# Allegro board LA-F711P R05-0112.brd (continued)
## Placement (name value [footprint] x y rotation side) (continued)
CZ115  0.1U_0201_10V6K  [C_0201]  196.24 7.58 90 top
CZ116  0.1U_0201_10V6K  [C_0201]  285.91 9.49 90 top
CZ117  470P_0402_50V7K  [C_0402]  286.67 9.55 90 top
CZ118  470P_0402_50V7K  [C_0402]  287.56 9.55 90 top
CZ119  0.1U_0201_10V6K  [C_0201]  311.31 69.43 180 top
CZ120  0.1U_0201_10V6K  [C_0201]  331.9 45.36 270 top
CZ121  470P_0402_50V7K  [C_0402]  330.63 45.06 270 top
CZ122  0.1U_0201_10V6K  [C_0201]  288.32 9.49 90 top
CZ124  2200P_0402_50V7K  [C_0402]  311.56 68.67 180 top
CZ125  0.1U_0201_10V6K  [C_0201]  332.26 22.32 90 top
CZ126  220P_0402_50V7K  [C_0402]  333.02 22.44 90 top
CZ127  1000P_0402_50V7K  [C_0402]  333.91 22.44 90 top
CZ128  0.1U_0201_10V6K  [C_0201]  334.67 22.44 90 top
CZ129  0.1U_0201_10V6K  [C_0201]  263.44 9.64 90 top
CZ130  470P_0402_50V7K  [C_0402]  264.21 9.73 90 top
CZ150  0.1U_0402_10V7K  [C_0402]  361.29 44.75 90 top
CZ151  0.1U_0402_10V7K  [C_0402]  360.39 44.78 90 top
CZ152  0.22U_0402_10V6K  [C_0402]  359.02 44.89 90 top
CZ153  0.22U_0402_10V6K  [C_0402]  358.13 44.91 90 top
CZ154  .1U_0402_16V7K  [C_0402]  356.5 48.93 270 top
CZ155  .1U_0402_16V7K  [C_0402]  359.93 51.56 90 top
CZ197  470P_0402_50V7K  [C_0402]  330.41 50.26 90 top
CZ198  100P_0402_50V8J  [C_0402]  325.91 63.34 90 bottom
CZ544  0.1U_0402_25V6  [C_0402]  142.4 86.51 0 bottom
CZ1200  0.1U_0402_25V6K  [C_0402]  125.45 99.35 270 bottom
DA1  AZ5123-02S.R7G_SOT23-3  [L03ESDL5V0CC3-2_SOT23-3]  353.11 29.46 180 bottom
DA2  -  [L03ESDL5V0CC3-2_SOT23-3]  348.28 29.59 180 bottom
DA3  AZ5123-02S.R7G_SOT23-3  [L03ESDL5V0CC3-2_SOT23-3]  354.99 36.7 315 bottom
DA6  -  [L03ESDL5V0CC3-2_SOT23-3]  345.41 23.74 90 top
DA7  -  [L03ESDL5V0CC3-2_SOT23-3]  345.41 19.74 90 top
DA8  RB751S40T1G_SOD523-2  [RB520SM-30T2R_EMD2-2]  336.38 28.42 0 top
DE1  BZV55-B5V6_SOD80C2  [BZV55-B5V1_SOD80C2]  208.8 69.3 90 bottom
DE2  RB751S40T1G_SOD523-2  [RB520SM-30T2R_EMD2-2]  315.43 56.26 270 top
DH1  RB751S40T1G_SOD523-2  [RB520SM-30T2R_EMD2-2]  195.58 6.08 90 bottom
DH2  RB751S40T1G_SOD523-2  [RB520SM-30T2R_EMD2-2]  192.73 7.67 0 bottom
DH3  RB751S40T1G_SOD523-2  [RB520SM-30T2R_EMD2-2]  201.14 14.36 270 top
DI1  -  [L05ESDL5V0NA-4_SLP2510P8-10-9]  19.21 90.39 270 top
DI2  -  [AZC199-02SPR7G_SOT23-3]  20.9 90.07 270 bottom
DI3  -  [AZC199-02SPR7G_SOT23-3]  79.9 122.07 90 bottom
DI4  -  [L05ESDL5V0NA-4_SLP2510P8-10-9]  354.36 70.19 90 bottom
DI5  -  [AZC199-02SPR7G_SOT23-3]  350.93 69.18 270 top
DI6  -  [L05ESDL5V0NA-4_SLP2510P8-10-9]  84.23 123.79 180 bottom
DT1  -  [1N4148WS-7-F_SOD323-2]  32.76 103.53 0 bottom
DT2  -  [1N4148WS-7-F_SOD323-2]  32.76 105.31 0 bottom
DT3  -  [1N4148WS-7-F_SOD323-2]  36.61 107.22 90 bottom
DT4  -  [L30ESD24VC3-2_SOT23-3]  13.76 124.51 0 bottom
DT5  AZ5B75-01B.R7G_CSP0603P2Y2  [ESD101-B1-02ELS_TSSLP-2-4-2]  13.64 107.98 90 bottom
DT6  AZ5B75-01B.R7G_CSP0603P2Y2  [ESD101-B1-02ELS_TSSLP-2-4-2]  13.64 109.43 270 bottom
DT9  AZ5B75-01B.R7G_CSP0603P2Y2  [ESD101-B1-02ELS_TSSLP-2-4-2]  12.73 118.9 270 bottom
DT10  AZ5B75-01B.R7G_CSP0603P2Y2  [ESD101-B1-02ELS_TSSLP-2-4-2]  12.73 117.48 90 bottom
DT13  AZ5B75-01B.R7G_CSP0603P2Y2  [ESD101-B1-02ELS_TSSLP-2-4-2]  12.76 110.26 90 bottom
DT14  AZ5B75-01B.R7G_CSP0603P2Y2  [ESD101-B1-02ELS_TSSLP-2-4-2]  12.76 111.65 270 bottom
DT17  AZ5B75-01B.R7G_CSP0603P2Y2  [ESD101-B1-02ELS_TSSLP-2-4-2]  13.45 116.08 90 bottom
DT18  AZ5B75-01B.R7G_CSP0603P2Y2  [ESD101-B1-02ELS_TSSLP-2-4-2]  13.45 117.48 270 bottom
DT39  -  [L05ESDL5V0NA-4_SLP2510P8-10-9]  13 113.31 270 bottom
DT40  -  [L05ESDL5V0NA-4_SLP2510P8-10-9]  12.3 112.44 270 top
DV1  -  [BAT54CW_SOT323-3]  133.57 95.34 270 bottom
DV2  -  [BAT54CW_SOT323-3]  133.45 92.67 270 bottom
DV3  -  [BAT54CW_SOT323-3]  143.16 110.96 270 bottom
DV4  -  [AZC199-02SPR7G_SOT23-3]  126.5 102.33 90 bottom
DV5  -  [PJDLC05C_SOT23-3]  353.34 104.16 90 bottom
DV6  -  [PJDLC05C_SOT23-3]  353.34 100.1 90 bottom
DV11  RB751S40T1G_SOD523-2  [RB520SM-30T2R_EMD2-2]  143.46 97.18 180 bottom
DV12  RB751S40T1G_SOD523-2  [RB520SM-30T2R_EMD2-2]  146.69 93.19 180 bottom
DZ1  RB751S40T1G_SOD523-2  [RB520SM-30T2R_EMD2-2]  303.05 24.55 180 top
DZ2  RB751S40T1G_SOD523-2  [RB520SM-30T2R_EMD2-2]  303.05 25.74 180 top
DZ5  RB751S40T1G_SOD523-2  [RB520SM-30T2R_EMD2-2]  326.42 59.78 90 top
DZ6  RB751S40T1G_SOD523-2  [RB520SM-30T2R_EMD2-2]  330.61 59.78 90 top
DZ7  RB751S40T1G_SOD523-2  [RB520SM-30T2R_EMD2-2]  296.93 10.36 180 bottom
DZ8  -  [RB751S40T1G_SOD523-2]  299.42 12.79 0 bottom
DZ9  -  [BAT54CW_SOT323-3]  289.8 4.34 0 top
FD1  FIDUCIAL MARK~D  [FIDUCIAL_C40M80]  296.64 108.18 0 top
FD2  FIDUCIAL MARK~D  [FIDUCIAL_C40M80]  9.44 4.44 0 top
FD3  FIDUCIAL MARK~D  [FIDUCIAL_C40M80]  9.7 2.82 180 bottom
FD4  FIDUCIAL MARK~D  [FIDUCIAL_C40M80]  348.28 115.72 180 bottom
H1  -  [H_3P8]  71.63 79.8 0 top
H2  -  [H_3P8]  129.31 81.3 0 top
H3  -  [H_3P8]  70.11 52.5 0 top
H4  -  [H_3P8]  133.05 53.68 0 top
H5  -  [H_1P0N]  82.02 81.95 0 top
H6  -  [H_1P0N]  123.13 54.84 0 top
H7  -  [H_3P2]  328.24 29.36 180 bottom
H8  -  [H_3P2]  333.9 98.66 180 bottom
H9  H_2P6  [H_2P6-G]  6.3 122.8 0 top
H10  H_2P6  [H_2P6-G]  6.3 104.7 0 top
H11  H_5P2  [H_5P2-G]  6.6 18.6 180 bottom
H12  -  [H_2P4N]  5 3.2 0 top
H13  H_2P4  [H_2P4-G]  70.4 134.2 0 top
H14  H_2P4  [H_2P4-G]  111.1 2.9 180 bottom
H16  -  [H_3P8]  142.1 136 0 top
H17  H_4P6  [H_4P6-G]  186.1 3.95 180 bottom
H18  H_2P4  [H_2P4-G]  194.9 138.2 180 bottom
H19  -  [H_5P0X4P0N]  216.42 67.07 0 top
H20  -  [H_5P0X4P0N]  305.89 101.2 0 top
H21  H_2P4  [H_2P4-G]  304.6 122.9 0 top
H22  H_5P1  [H_5P1-G]  354.6 93.2 0 top
H23  H_5P2  [H_5P2-G]  365.6 18.6 180 bottom
H34  -  [H_3P3]  96.7 108.35 180 bottom
H35  -  [H_3P3]  131.1 108.35 180 bottom
H42  -  [H_0P7N]  366.45 54.95 0 top
H43  -  [H_0P9N]  353.4 45.75 0 top
H46  -  [H_2P4X1P8N]  217.1 73.2 0 top
H49  -  [H_3P2N]  219.42 61.07 0 top
JAPS1  ACES_50506-01841-P01  [ACES_50506-01841-P01_18P]  172.82 44.03 0 top
JCRT1  CCM_C070546HR015M29CZR  [CCM_C070546HR015M29CZR_15P-T]  364.8 102.53 90 bottom
JDB1  JXT_FP241AH-006GAAM  [JXT_FP241AH-006GAAM_6P]  52.99 99.89 270 bottom
JDEG1  JXT_FP241AH-010GAAM  [JXT_FP241AH-010GAAM_10P]  329.9 14.51 0 bottom
JDIMM1  LCN_DAN05-Q0406-0103  [LCN_DAN05-Q0406-0103_260P]  28.22 22.3 180 bottom
JDIMM2  LCN_DAN05-Q0406-0103  [LCN_DAN05-Q0406-0103_260P]  109.22 22.3 180 bottom
JEDP1  ACES_50398-04041-001  [ACES_50398-04041-001_40P]  123.65 106.42 180 bottom
JESPI  JXT_FP241AH-010GAAM  [JXT_FP241AH-010GAAM_10P]  265.08 22.95 0 bottom
JFAN1  ACES_50271-0040N-001  [ACES_50271-0040N-001_4P]  202.34 67.15 180 bottom
JHDMI1  CONCR_099BKAC19YBLCNF  [CONCR_099BKAC19YBLCNF_19P]  104.6 130.32 0 bottom
JHP1  SINGA_2SJ3095-059111F  [SINGA_2SJ3095-059111F_6P]  359.13 35.22 90 bottom
JIR1  ACES_50208-0060N-P01  [ACES_50208-0060N-P01_6P]  130.61 113.42 0 bottom
JKBTP1  CVILU_CF5020FD0RK-05-NH  [CVILU_CF5020FD0RK-05-NH_20P-T]  144.02 10 180 bottom
JLED1  CVILU_CF5006FD0R0-05-NH  [CVILU_CF5006FD0R0-05-NH_6P]  323.04 7.85 180 bottom
JLOM1  SANTA_130456-831  [SANTA_130456-831_13P-T]  326.43 126.48 0 bottom
JNGFF1  LCN_DAN05-67406-0102  [LCN_DAN05-67406-0102_75P-T]  294.72 38.61 270 bottom
JNGFF2  CONCR_213BAAA42FA  [CONCR_213BAAA42FA_75P]  324.65 53.13 0 bottom
JNGFF3  LCN_DAN05-67356-0103  [LCN_DAN05-67356-0103_75P]  360.55 9.42 180 bottom
JRTC1  ACES_50271-0020N-001  [ACES_50271-0020N-001_2P]  292.9 4.95 90 bottom
JSATA1  ACES_59003-02006-002  [ACES_59003-02006-002_20P]  255.35 13.52 0 bottom
JSD1  T-SOL_156-2000302608_NR  [T-SOL_156-2000302608_19P_NR]  32.52 59.9 90 bottom
JSIM1  T-SOL_5-991503004000-6  [T-SOL_5-991503004000-6_8P-T]  356.08 52.76 270 bottom
JSPI1  ACES_50506-02041-P01  [ACES_50506-02041-P01_20P]  230.64 8.22 180 bottom
JSPK1  ACES_50278-00401-001  [ACES_50278-00401-001_4P]  339.85 24 270 bottom
JTAG1  @SHORT PADS~D  [SHORTPADS]  327.76 39.25 270 top
JUSB1  J-L_TNBNRAC70030009  [J-L_TNBNRAC70030009_9P]  357.15 65.7 270 bottom
JUSB2  J-L_TNBNRAC70030009  [J-L_TNBNRAC70030009_9P]  15.05 94.71 90 bottom
JUSB3  J-L_TNBNRAC70030009  [J-L_TNBNRAC70030009_9P]  89.6 126.25 0 bottom
JUSBC1  JAE_DX07BD24JJ2  [JAE_DX07BD24JJ2_24P-T]  7.7 111.13 90 bottom
JUSH1  CVILU_CF5026FD0RK-05-NH  [CVILU_CF5026FD0RK-05-NH_26P-T]  312.33 8.2 180 bottom
JXDP1  SAMTE_BSH-030-01-L-D-A  [SAMTE_BSH-030-01-L-D-A_60P]  32.67 39.21 0 top
LA5  BLM15PX600SN1D_2P  [MURAT_BLM15PX600SN1D_2P]  346.38 45.9 90 top
LA6  BLM15PD800SN1D_2P  [MURAT_BLM15PD800SN1D_2P]  348.11 24.69 180 top
LA7  BLM15PD800SN1D_2P  [MURAT_BLM15PD800SN1D_2P]  348.11 22.53 180 top
LA8  BLM15PD800SN1D_2P  [MURAT_BLM15PD800SN1D_2P]  348.11 20.75 180 top
LA9  BLM15PD800SN1D_2P  [MURAT_BLM15PD800SN1D_2P]  348.11 18.72 180 top
LA10  BLM15PX330SN1D_2P  [MURAT_BLM15PX330SN1D_2P]  347.93 35.73 270 bottom
LA11  BLM15PX330SN1D_2P  [MURAT_BLM15PX330SN1D_2P]  348.15 38 90 bottom
LA12  BLM15PX600SN1D_2P  [MURAT_BLM15PX600SN1D_2P]  342.4 32.29 270 bottom
LA13  HCB2012VF-601T20_2P  [TAI-T_HCB2012KF-121T50_2P]  333.13 33.53 270 top
LA14  BLM15PX600SN1D_2P  [MURAT_BLM15PX600SN1D_2P]  337.99 31.31 270 top
LA15  BLM15PX330SN1D_2P  [MURAT_BLM15PX330SN1D_2P]  349.18 32.28 270 top
LA16  BLM15PX330SN1D_2P  [MURAT_BLM15PX330SN1D_2P]  353.39 32.05 270 top
LC1  BLM15GA750SN1D_2P  [MURAT_BLM15GA750SN1D_2P]  222.14 39.15 180 top
LC2  BLM15GA750SN1D_2P  [MURAT_BLM15GA750SN1D_2P]  186.89 46.7 270 bottom
LC3  BLM15GA750SN1D_2P  [MURAT_BLM15GA750SN1D_2P]  191.08 47.65 270 bottom
LED3  LTW-C193DC-C_WHITE  [LED_LTW-C193DC-C_2P]  351.05 123.26 0 top
LGA1  -  [LNG2DMTR_LGA12_2X2]  271.03 4.58 0 top
LI3  EXC24CQ900U_4P  [PANAS_EXC24CQ900U_4P]  21.88 87.32 90 bottom
LI4  EXC24CQ900U_4P  [PANAS_EXC24CQ900U_4P]  76.89 123.04 270 bottom
LI7  EXC24CQ900U_4P  [PANAS_EXC24CQ900U_4P]  339.88 72.48 180 top
LI8  MCM1012B900F06BP_4P  [INPAQ_MCM1012B900F06BP_4P]  326.04 52.8 90 top
LI9  MCM1012B900F06BP_4P  [INPAQ_MCM1012B900F06BP_4P]  290.86 37.56 0 bottom
LI16  HCM1012GH900BP_4P  [INPAQ_HCM1012GH900BP_4P]  331.42 52.69 90 top
LI17  HCM1012GH900BP_4P  [INPAQ_HCM1012GH900BP_4P]  333.32 50.6 90 top
LL1  4.7UH_BRC2012T4R7MD_20%  [TAIYO_BRC2012T4R7MD_2P]  326.8 86.58 0 top
LT11  BLM18KG331SN1D_2P  [MURAT_BLM18KG331SN1D_2P]  18.7 117.75 0 top
LT601  BLM18KG331SN1D_2P  [MURAT_BLM18KG331SN1D_2P]  22.72 119.42 270 top
LT602  BLM18KG331SN1D_2P  [MURAT_BLM18KG331SN1D_2P]  20.35 119.47 0 bottom
LT603  BLM18KG331SN1D_2P  [MURAT_BLM18KG331SN1D_2P]  21.19 118.09 270 top
LT604  BLM18KG331SN1D_2P  [MURAT_BLM18KG331SN1D_2P]  27.94 117.31 180 top
LT605  BLM18KG331SN1D_2P  [MURAT_BLM18KG331SN1D_2P]  27.67 113.9 270 top
LV1  BLM15PX221SN1D_2P  [MURAT_BLM15PX221SN1D_2P]  113.19 103.6 270 bottom
LV3  HCM1012GH900BP_4P  [TAIYO_MCF12102G900-T_4P]  101.48 123.15 90 top
LV6  HCM1012GH900BP_4P  [TAIYO_MCF12102G900-T_4P]  104.98 123.15 90 top
LV9  HCM1012GH900BP_4P  [TAIYO_MCF12102G900-T_4P]  111.84 124.17 90 top
LV12  HCM1012GH900BP_4P  [TAIYO_MCF12102G900-T_4P]  108.61 123.22 90 top
LV14  BLM15PX600SN1D_2P  [MURAT_BLM15PX600SN1D_2P]  321.97 74.13 0 top
LV16  BLM15BB470SN1D_2P  [MURAT_BLM15BB470SN1D_2P]  358.69 104.17 90 top
LV17  BLM15BB470SN1D_2P  [MURAT_BLM15BB470SN1D_2P]  358.69 101.76 90 top
LV18  BLM15BB470SN1D_2P  [MURAT_BLM15BB470SN1D_2P]  358.82 98.96 90 top
LV27  EXC24CQ900U_4P  [PANAS_EXC24CQ900U_4P]  131.23 101.9 270 bottom
LV30  BLM15PX600SN1D_2P  [MURAT_BLM15PX600SN1D_2P]  332.02 71.32 270 top
LZ1  EXC24CQ900U_4P  [PANAS_EXC24CQ900U_4P]  118.01 102.33 0 bottom
LZ2  BLM15AX221SN1_2P  [MURAT_BLM15PX221SN1D_2P]  313.59 10.06 180 bottom
NOREF  -  []  6.3 104.7 0 top
NOREF#2  -  []  142.1 136 0 top
NOREF#3  -  []  333.9 98.66 0 top
NOREF#4  -  []  111.1 2.9 0 top
NOREF#5  -  []  190.93 86.83 90 top
NOREF#6  -  []  111.17 35.46 0 top
NOREF#7  -  []  323.55 7.89 0 top
NOREF#8  -  []  98.22 35.46 0 top
NOREF#9  -  []  70.4 134.2 0 top
NOREF#10  -  []  71.63 79.8 0 top
NOREF#11  -  []  181.78 108.22 0 top
NOREF#12  -  []  96.7 108.35 0 top
NOREF#13  -  []  70.11 52.5 0 top
NOREF#14  -  []  365.6 18.6 0 top
NOREF#15  -  []  354.6 93.2 0 top
NOREF#16  -  []  304.6 122.9 0 top
NOREF#17  -  []  133.05 53.68 0 top
NOREF#18  -  []  96.31 181.27 0 top
NOREF#19  -  []  6.6 18.6 0 top
NOREF#20  -  []  328.24 29.36 0 top
NOREF#21  -  []  186.1 3.95 0 top
NOREF#22  -  []  131.1 108.35 0 top
NOREF#23  -  []  129.31 81.3 0 top
NOREF#24  -  []  168.11 -51.31 0 top
NOREF#25  -  []  281.77 189.06 0 top
NOREF#26  -  []  6.3 122.8 0 top
NOREF#27  -  []  182.42 93.43 0 top
NOREF#28  -  []  5 3.2 0 top
NOREF#29  -  []  162.8 127.09 0 top
NOREF#30  -  []  202.68 123.53 180 bottom
NOREF#31  -  []  204.14 101.94 180 bottom
NOREF#32  -  []  79.59 34.23 180 bottom
PBATT1  DEREN_40-42251-01001RHF  [DEREN_40-42251-01001RHF_10P-T]  23.25 11.9 180 bottom
PC1  2200P_0402_50V7K  [C_0402]  12.35 5.04 270 top
PC2  2200P_0402_50V7K  [C_0402]  296.32 6.06 270 top
PC3  1U_0603_25V7K  [C_0603]  296.07 9.11 270 top
PC4  0.022U_0603_50V7K  [C_0603]  58.96 112.27 270 top
PC5  1000P_0603_50V7K  [C_0603]  65.18 115.53 270 bottom
PC6  0.022U_0603_50V7K  [C_0603]  69.52 121.33 270 top
PC7  0.1U_0603_25V7K  [C_0603]  68.13 116.36 270 top
PC8  10U_0805_25V6K  [C_0805]  65.11 114.58 0 top
PC9  0.1U_0402_25V6  [C_0402]  72.22 116.6 90 top
PC10  2.2U_0402_6.3V6M  [C_0402]  73.2 111.45 90 bottom
PC11  1000P_0603_50V7K  [C_0603]  68.94 115.34 0 bottom
PC100  68P_0402_50V8J  [C_0402]  83.29 5.88 90 top
PC102  0.1U_0603_25V7K  [C_0603]  91.16 3.8 90 bottom
PC103  100P_0402_50V8J  [C_0402]  83.29 5.88 90 bottom
PC104  10U_0805_25V6K  [C_0805]  84.64 5.15 90 top
PC105  10U_0805_25V6K  [C_0805]  84.64 5.16 90 bottom
PC106  22U_0805_6.3V6M  [C_0805]  103.79 7.8 270 bottom
PC107  22U_0805_6.3V6M  [C_0805]  101.99 9.78 90 bottom
PC108  22U_0805_6.3V6M  [C_0805]  103.79 9.78 90 bottom
PC109  22U_0805_6.3V6M  [C_0805]  101.99 7.8 270 bottom
PC110  22U_0805_6.3V6M  [C_0805]  100.19 9.78 90 bottom
PC111  4.7U_0603_6.3V6K  [C_0603]  90.27 10.1 90 bottom
PC112  680P_0603_50V7K  [C_0603]  88.82 6.32 0 top
PC113  1000P_0402_50V7K  [C_0402]  87.83 10.46 90 bottom
PC114  0.1U_0603_25V7K  [C_0603]  128.06 129.76 270 top
PC115  0.1U_0402_25V6  [C_0402]  126.75 134.21 90 bottom
PC116  100P_0402_50V8J  [C_0402]  126.75 134.21 90 top
PC117  10U_0805_25V6K  [C_0805]  127.78 134.66 0 top
PC118  10U_0805_25V6K  [C_0805]  127.78 134.66 0 bottom
PC119  4.7U_0603_6.3V6K  [C_0603]  121.84 129.21 0 top
PC120  22U_0805_6.3V6M  [C_0805]  136.19 129.16 0 bottom
PC121  22U_0805_6.3V6M  [C_0805]  134.86 132.73 0 bottom
PC122  22U_0805_6.3V6M  [C_0805]  136.11 130.98 0 top
PC123  22U_0805_6.3V6M  [C_0805]  134.95 132.73 0 top
PC124  22U_0805_6.3V6M  [C_0805]  136.16 130.88 0 bottom
PC125  680P_0603_50V7K  [C_0603]  122.98 128.75 90 bottom
PC126  4.7U_0603_6.3V6K  [C_0603]  120.65 130.92 270 top
PC127  1000P_0402_50V7K  [C_0402]  120.78 132.56 90 top
PC128  4.7U_0402_6.3V6M  [C_0402]  118.59 128.68 0 bottom
PC129  22U_0805_6.3V6M  [C_0805]  100.15 7.8 270 bottom
PC130  22U_0805_6.3V6M  [C_0805]  136.18 129.18 0 top
PC133  1U_0402_25V6K  [C_0402]  78.44 6.26 180 top
PC134  100P_0402_50V8J  [C_0402]  78.44 5.39 180 top
PC135  100P_0402_50V8J  [C_0402]  78.43 4.52 180 top
PC136  1U_0402_25V6K  [C_0402]  78.42 3.65 180 top
PC137  1U_0402_25V6K  [C_0402]  78.44 6.27 180 bottom
PC138  100P_0402_50V8J  [C_0402]  78.45 5.39 180 bottom
PC139  100P_0402_50V8J  [C_0402]  78.43 4.53 180 bottom
PC140  100P_0402_50V8J  [C_0402]  78.42 3.65 180 bottom
PC200  10U_0805_25V6K  [C_0805]  41.73 7.71 90 top
PC201  10U_0805_25V6K  [C_0805]  41.71 7.71 90 bottom
PC202  0.1U_0402_25V6  [C_0402]  40.39 8.01 90 bottom
PC203  2200P_0402_50V7K  [C_0402]  40.38 8.03 90 top
PC204  680P_0603_50V7K  [C_0603]  54.46 8.58 0 top
PC205  0.1U_0603_16V7K  [C_0603]  52.01 5.5 90 top
PC206  1U_0402_6.3V6K  [C_0402]  48.41 4.54 270 top
PC207  2.2U_0402_6.3V6M  [C_0402]  47.59 4.56 270 bottom
PC208  330P_0402_50V7K  [C_0402]  44.88 3.64 0 bottom
PC209  22U_0603_6.3V6M  [C_0603]  48.22 10.15 90 bottom
PC210  22U_0603_6.3V6M  [C_0603]  62.4 5.8 270 bottom
PC211  22U_0603_6.3V6M  [C_0603]  62.4 5.8 270 top
PC212  22U_0603_6.3V6M  [C_0603]  61.13 5.8 270 top
PC213  22U_0603_6.3V6M  [C_0603]  61.13 5.8 270 bottom
PC214  10U_0603_6.3V6M  [C_0603]  59.86 5.8 270 bottom
PC216  2200P_0402_50V7K  [C_0402]  64.69 5.56 270 bottom
PC217  100P_0402_50V8J  [C_0402]  64.69 5.56 270 top
PC218  1U_0402_6.3V6K  [C_0402]  44.96 10.24 0 bottom
PC219  22U_0603_6.3V6M  [C_0603]  46.65 11.32 180 bottom
PC221  0.1U_0402_25V6  [C_0402]  42.16 10.48 90 bottom
PC222  0.1U_0402_25V6  [C_0402]  43.05 10.49 90 top
PC223  10U_0603_6.3V6M  [C_0603]  59.86 5.8 270 top
PC302  680P_0603_50V7K  [C_0603]  170.77 2.63 180 top
PC303  100P_0402_50V8J  [C_0402]  166.84 1.61 0 top
PC304  0.1U_0603_25V7K  [C_0603]  169.4 3.53 270 bottom
PC305  10U_0603_25V6M  [C_0603]  166.92 2.25 0 bottom
PC306  10U_0603_25V6M  [C_0603]  166.92 3.45 0 bottom
PC307  330P_0402_50V7K  [C_0402]  167.88 10.54 0 bottom
PC308  22U_0603_6.3V6M  [C_0603]  177.63 10.17 180 top
PC309  22U_0603_6.3V6M  [C_0603]  177.63 7.63 180 bottom
PC310  22U_0603_6.3V6M  [C_0603]  177.63 7.76 180 top
PC311  22U_0603_6.3V6M  [C_0603]  177.63 10.05 180 bottom
PC312  4.7U_0603_6.3V6K  [C_0603]  171.29 7.63 0 bottom
PC313  4.7U_0603_6.3V6K  [C_0603]  171.28 8.83 0 bottom
PC314  0.1U_0402_25V6  [C_0402]  165.77 9.4 90 top
PC315  22U_0603_6.3V6M  [C_0603]  177.63 8.85 180 bottom
PC316  22U_0603_6.3V6M  [C_0603]  177.63 8.98 180 top
PC401  22U_0603_6.3V6M  [C_0603]  142.73 61.49 180 bottom
PC403  470P_0402_50V7K  [C_0402]  142.01 59.92 270 bottom
PC404  10U_0603_10V6M  [C_0603]  155.84 57.73 270 bottom
PC405  100P_0402_50V8J  [C_0402]  154.83 60.02 90 bottom
PC407  0.1U_0402_25V6  [C_0402]  155.72 60.02 90 bottom
PC408  10U_0603_10V6M  [C_0603]  154.58 57.71 270 bottom
PC409  470P_0402_50V7K  [C_0402]  152.49 63.09 90 bottom
PC410  22U_0603_6.3V6M  [C_0603]  147.43 65.23 0 bottom
PC411  22U_0603_6.3V6M  [C_0603]  147.43 64.03 0 bottom
PC412  22U_0603_6.3V6M  [C_0603]  142.73 62.76 180 bottom
PC415  0.1U_0402_25V6  [C_0402]  153.84 57.11 0 top
PC501  22U_0603_6.3V6M  [C_0603]  122.94 7.91 90 bottom
PC502  22U_0603_6.3V6M  [C_0603]  116.97 4.81 0 bottom
PC503  68P_0402_50V8J  [C_0402]  121.5 7.92 180 bottom
PC504  22U_0603_6.3V6M  [C_0603]  124.32 7.94 90 bottom
PC505  .1U_0402_16V7K  [C_0402]  122.35 7.95 90 top
PC506  680P_0402_50V7K  [C_0402]  128.43 4.52 90 bottom
PC508  4.7U_0603_6.3V6K  [C_0603]  151.68 129.44 180 top
PC509  0.01UF_0402_25V7K  [C_0402]  146.03 127.99 270 top
PC510  .1U_0402_16V7K  [C_0402]  152 126.53 270 top
PC511  22U_0805_6.3V6M  [C_0805]  147.09 129.69 0 top
PC513  .1U_0402_16V7K  [C_0402]  69.83 6.38 270 bottom
PC514  4.7U_0603_6.3V6K  [C_0603]  69.96 9.45 0 bottom
PC515  0.01UF_0402_25V7K  [C_0402]  76.64 7.67 270 bottom
PC516  22U_0603_6.3V6M  [C_0603]  74.64 9.52 180 bottom
PC800  1U_0201_6.3V6M  [C_0201]  112.99 61.35 0 top
PC801  1U_0201_6.3V6M  [C_0201]  112.99 60.76 0 top
PC802  1U_0201_6.3V6M  [C_0201]  107.65 74.36 180 top
PC803  1U_0201_6.3V6M  [C_0201]  98.19 73.8 180 top
PC804  1U_0201_6.3V6M  [C_0201]  98.19 74.36 180 top
PC805  1U_0201_6.3V6M  [C_0201]  107.65 73.8 180 top
PC806  1U_0201_6.3V6M  [C_0201]  110.02 73.8 180 top
PC807  22U_0603_6.3V6M  [C_0603]  117.64 88.72 0 bottom
PC808  22U_0603_6.3V6M  [C_0603]  116.98 86.36 0 top
PC809  22U_0603_6.3V6M  [C_0603]  111.6 85.73 180 top
PC810  22U_0603_6.3V6M  [C_0603]  111.59 86.28 180 bottom
PC811  22U_0603_6.3V6M  [C_0603]  111.62 84.52 180 top
PC812  22U_0603_6.3V6M  [C_0603]  117.64 87.55 0 top
PC813  22U_0603_6.3V6M  [C_0603]  110.8 87.49 180 bottom
PC815  22U_0603_6.3V6M  [C_0603]  117.64 88.77 0 top
PC816  22U_0603_6.3V6M  [C_0603]  110.81 87.82 180 top
PC817  22U_0603_6.3V6M  [C_0603]  117.64 87.5 0 bottom
PC818  22U_0603_6.3V6M  [C_0603]  116.95 86.21 0 bottom
PC819  1U_0201_6.3V6M  [C_0201]  103.99 61.08 0 top
PC820  1U_0201_6.3V6M  [C_0201]  102.91 73.8 180 top
PC821  1U_0201_6.3V6M  [C_0201]  105.27 74.36 180 top
PC822  1U_0201_6.3V6M  [C_0201]  98.03 62.95 180 top
PC823  1U_0201_6.3V6M  [C_0201]  98.63 62.96 0 top
PC824  1U_0201_6.3V6M  [C_0201]  103.45 63.32 180 top
PC825  1U_0201_6.3V6M  [C_0201]  97.95 61.04 180 top
PC826  1U_0201_6.3V6M  [C_0201]  100.57 74.36 180 top
PC827  1U_0201_6.3V6M  [C_0201]  100.57 73.8 180 top
PC828  1U_0201_6.3V6M  [C_0201]  103.45 62.76 180 top
PC829  1U_0201_6.3V6M  [C_0201]  102.91 74.36 180 top
PC830  1U_0201_6.3V6M  [C_0201]  105.27 73.8 180 top
PC831  1U_0201_6.3V6M  [C_0201]  110.02 74.36 180 top
PC832  1U_0201_6.3V6M  [C_0201]  97.93 61.82 180 top
PC833  1U_0201_6.3V6M  [C_0201]  103.99 61.64 0 top
PC834  10U_0402_6.3V6M  [C_0402]  111.4 85.24 180 bottom
PC835  10U_0402_6.3V6M  [C_0402]  111.18 86.78 180 top
PC836  10U_0402_6.3V6M  [C_0402]  117.22 84.45 0 top
PC837  10U_0402_6.3V6M  [C_0402]  117.22 85.32 0 top
PC838  10U_0402_6.3V6M  [C_0402]  110.67 88.87 180 top
PC839  10U_0402_6.3V6M  [C_0402]  117.32 85.14 0 bottom
PC840  10U_0402_6.3V6M  [C_0402]  113.53 73.06 270 top
PC841  22U_0603_6.3V6M  [C_0603]  114.59 73.95 0 top
PC842  22U_0603_6.3V6M  [C_0603]  116.91 91.22 0 top
PC843  22U_0603_6.3V6M  [C_0603]  117.71 89.99 0 top
PC844  22U_0603_6.3V6M  [C_0603]  113.64 74.08 180 top
PC848  470U_X_2VM_R6M  [C_X]  61.39 66.32 270 bottom
PC849  470U_X_2VM_R6M  [C_X]  59.74 67.21 270 top
PC851  1U_0201_6.3V6M  [C_0201]  104 60.5 0 top
PC852  1U_0201_6.3V6M  [C_0201]  115.39 61.18 0 top
PC902  0.1U_0402_25V6  [C_0402]  23.73 30.19 270 top
PC903  2200P_0402_50V7K  [C_0402]  22.81 30.21 270 top
PC904  10U_0805_25VAK  [C_0805]  20.12 37.49 0 top
PC905  10U_0805_25VAK  [C_0805]  20.12 37.49 0 bottom
PC906  10U_0805_25VAK  [C_0805]  18.48 37.49 180 bottom
PC909  15U_B2_25VM_R100M  [C_B2]  18.57 34.48 180 bottom
PC911  10U_0805_25VAK  [C_0805]  18.48 37.49 180 top
PC913  10U_0805_25VAK  [C_0805]  34.69 7.64 0 bottom
PC914  10U_0805_25VAK  [C_0805]  34.69 9.42 0 top
PC915  10U_0805_25VAK  [C_0805]  34.69 7.64 0 top
PC916  10U_0805_25VAK  [C_0805]  34.69 9.42 0 bottom
PC921  15U_B2_25VM_R100M  [C_B2]  32.5 6.86 90 bottom
PC922  15U_B2_25VM_R100M  [C_B2]  29.26 6.86 90 bottom
PC925  4.7U_0402_6.3V6M  [C_0402]  14.07 35.55 270 top
PC926  1U_0402_25V6K  [C_0402]  12.5 35.4 180 bottom
PC927  1U_0402_25V6K  [C_0402]  12.51 34.53 180 bottom
PC928  0.1U_0402_25V6  [C_0402]  28.16 2.76 270 top
PC929  2200P_0402_50V7K  [C_0402]  27.29 2.76 270 top
PC930  0.22U_0603_25V7K  [C_0603]  15.36 32.57 180 bottom
PC931  1U_0603_25V6  [C_0603]  12.65 39.37 270 top
PC932  1U_0402_6.3V6K  [C_0402]  10.36 32.16 270 bottom
PC933  1U_0402_6.3V6K  [C_0402]  11.54 37.92 90 top
PC934  0.22U_0603_25V7K  [C_0603]  9.43 28.03 90 top
PC935  10U_0805_25VAK  [C_0805]  21.87 2.22 180 top
PC936  10U_0805_25VAK  [C_0805]  23.02 2.15 0 top
PC937  4700P_0402_25V7K  [C_0402]  24.06 6.46 180 top
PC938  10P_0402_50V8J  [C_0402]  6.4 38.56 90 top
PC939  0.1U_0402_25V6  [C_0402]  9.17 31.08 90 bottom
PC940  680P_0603_50V7K  [C_0603]  11.68 24.24 270 top
PC941  680P_0603_50V7K  [C_0603]  12.79 16.5 90 top
PC942  1U_0402_25V6K  [C_0402]  8.16 31.08 90 bottom
PC943  560P_0402_50V7K  [C_0402]  7.16 34.44 0 bottom
PC944  0.012U_0402_16V7K~D  [C_0402]  7.21 35.71 0 bottom
PC945  1U_0402_25V6K  [C_0402]  7.78 29.49 180 bottom
PC946  0.22U_0402_25V6K  [C_0402]  7.27 31.08 90 bottom
PC947  0.1U_0402_25V6  [C_0402]  5.25 34.75 90 bottom
PC949  0.1U_0402_25V6  [C_0402]  15.62 47.23 180 top
PC950  0.1U_0402_25V6  [C_0402]  8.05 32.87 180 bottom
PC951  10U_0805_25VAK  [C_0805]  18.48 39.22 180 top
PC952  10U_0805_25VAK  [C_0805]  20.13 39.2 0 bottom
PC953  10U_0805_25VAK  [C_0805]  18.48 39.22 180 bottom
PC954  10U_0805_25VAK  [C_0805]  20.13 39.2 0 top
PC955  0.1U_0402_25V6  [C_0402]  14 38.07 90 top
PC956  100P_0402_50V8J  [C_0402]  34.59 4.55 270 bottom
PC957  100P_0402_50V8J  [C_0402]  34.59 4.55 270 top
PC958  1U_0402_25V6K  [C_0402]  35.48 4.55 270 top
PC959  1U_0402_25V6K  [C_0402]  35.48 4.55 270 bottom
PC1001  22U_0603_6.3V6M  [C_0603]  93.5 69.61 0 top
PC1002  22U_0603_6.3V6M  [C_0603]  92.13 64.61 270 top
PC1003  22U_0603_6.3V6M  [C_0603]  90.19 64.49 180 top
PC1004  22U_0603_6.3V6M  [C_0603]  66.02 66.13 0 bottom
PC1005  22U_0603_6.3V6M  [C_0603]  86.45 63.27 0 top
PC1006  22U_0603_6.3V6M  [C_0603]  93.5 68.4 0 top
PC1007  22U_0603_6.3V6M  [C_0603]  92.53 68.4 180 top
PC1008  22U_0603_6.3V6M  [C_0603]  86.45 64.49 0 top
PC1009  22U_0603_6.3V6M  [C_0603]  90.19 63.27 180 top
PC1010  22U_0603_6.3V6M  [C_0603]  86.43 70.82 0 top
PC1011  22U_0603_6.3V6M  [C_0603]  86.45 69.61 0 top
PC1012  22U_0603_6.3V6M  [C_0603]  88.78 70.82 0 top
PC1013  22U_0603_6.3V6M  [C_0603]  92.53 70.82 180 top
PC1014  22U_0603_6.3V6M  [C_0603]  93.5 70.82 0 top
PC1015  22U_0603_6.3V6M  [C_0603]  88.78 68.4 0 top
PC1016  22U_0603_6.3V6M  [C_0603]  66.02 66.13 0 top
PC1017  22U_0603_6.3V6M  [C_0603]  92.53 69.61 180 top
PC1018  22U_0603_6.3V6M  [C_0603]  86.43 68.4 0 top
PC1019  22U_0603_6.3V6M  [C_0603]  88.78 69.61 0 top
PC1021  330U_D2_2.5V_R6M  [C_D2]  70.22 87.83 180 bottom
PC1022  330U_D2_2.5V_R6M  [C_D2]  101.39 89.56 90 top
PC1023  10U_0402_6.3V6M  [C_0402]  86.41 67.33 0 top
PC1024  10U_0402_6.3V6M  [C_0402]  91.38 72.74 180 top
PC1025  10U_0402_6.3V6M  [C_0402]  86.41 66.44 0 top
PC1026  10U_0402_6.3V6M  [C_0402]  87.7 61.46 0 top
PC1027  10U_0402_6.3V6M  [C_0402]  86.4 65.55 0 top
PC1028  10U_0402_6.3V6M  [C_0402]  92.22 72.74 0 top
PC1029  10U_0402_6.3V6M  [C_0402]  86.37 72.72 0 top
PC1030  10U_0402_6.3V6M  [C_0402]  91.38 71.85 180 top
PC1031  10U_0402_6.3V6M  [C_0402]  92.22 71.85 0 top
PC1032  10U_0402_6.3V6M  [C_0402]  86.37 71.85 0 top
PC1041  22U_0603_6.3V6M  [C_0603]  106.7 69.36 0 top
PC1042  22U_0603_6.3V6M  [C_0603]  103.37 69.36 180 top
PC1043  22U_0603_6.3V6M  [C_0603]  110.33 63.01 180 top
PC1044  22U_0603_6.3V6M  [C_0603]  111.29 63.01 0 top
PC1045  22U_0603_6.3V6M  [C_0603]  105.62 63.01 180 top
PC1046  22U_0603_6.3V6M  [C_0603]  111.41 68.72 0 top
PC1047  22U_0603_6.3V6M  [C_0603]  80.53 86.11 180 top
PC1048  22U_0603_6.3V6M  [C_0603]  110.47 69.92 180 top
PC1049  22U_0603_6.3V6M  [C_0603]  101.51 86.13 0 top
PC1050  22U_0603_6.3V6M  [C_0603]  101.51 86.13 0 bottom
PC1051  22U_0603_6.3V6M  [C_0603]  106.58 63.01 0 top
PC1052  22U_0603_6.3V6M  [C_0603]  103.37 68.16 180 top
PC1053  22U_0603_6.3V6M  [C_0603]  100.67 62.83 90 top
PC1054  22U_0603_6.3V6M  [C_0603]  105.72 68.16 180 top
PC1055  22U_0603_6.3V6M  [C_0603]  103.21 65.09 180 top
PC1056  22U_0603_6.3V6M  [C_0603]  106.7 68.16 0 top
PC1074  10U_0402_6.3V6M  [C_0402]  100.8 71.64 0 top
PC1075  10U_0402_6.3V6M  [C_0402]  107.08 64.94 0 top
PC1076  10U_0402_6.3V6M  [C_0402]  107.13 64.06 0 top
PC1077  10U_0402_6.3V6M  [C_0402]  109.99 64.05 180 top
PC1078  10U_0402_6.3V6M  [C_0402]  103.57 64.04 180 top
PC1079  10U_0402_6.3V6M  [C_0402]  105.18 72.52 180 top
PC1080  10U_0402_6.3V6M  [C_0402]  114.5 62.86 180 top
PC1081  10U_0402_6.3V6M  [C_0402]  105.18 71.64 180 top
PC1082  10U_0402_6.3V6M  [C_0402]  106 72.52 0 top
PC1083  10U_0402_6.3V6M  [C_0402]  100.8 72.52 0 top
PC1084  10U_0402_6.3V6M  [C_0402]  103.45 72.52 180 top
PC1085  10U_0402_6.3V6M  [C_0402]  105.33 64.05 180 top
PC1086  10U_0402_6.3V6M  [C_0402]  111.84 64.05 0 top
PC1087  10U_0402_6.3V6M  [C_0402]  103.45 71.64 180 top
PC1088  1U_0201_6.3V6M  [C_0201]  86.99 61.33 180 top
PC1089  1U_0201_6.3V6M  [C_0201]  93.28 61.81 180 top
PC1090  1U_0201_6.3V6M  [C_0201]  94 73.49 180 top
PC1091  1U_0201_6.3V6M  [C_0201]  94.42 72.34 180 top
PC1092  1U_0201_6.3V6M  [C_0201]  95.02 72.33 270 top
PC1093  1U_0201_6.3V6M  [C_0201]  88.58 72.31 180 top
PC1094  1U_0201_6.3V6M  [C_0201]  88.58 72.88 180 top
PC1095  1U_0201_6.3V6M  [C_0201]  94.42 72.9 180 top
PC1096  1U_0201_6.3V6M  [C_0201]  86.99 61.91 180 top
PC1097  1U_0201_6.3V6M  [C_0201]  89.18 72.31 0 top
PC1098  1U_0201_6.3V6M  [C_0201]  89.18 72.88 0 top
PC1099  1U_0201_6.3V6M  [C_0201]  93.89 61.72 0 top
PC1103  10U_0402_6.3V6M  [C_0402]  107.74 71.64 0 top
PC1104  10U_0402_6.3V6M  [C_0402]  107.74 72.52 0 top
PC1105  10U_0402_6.3V6M  [C_0402]  111.86 64.95 0 top
PC1106  10U_0402_6.3V6M  [C_0402]  109.75 64.94 180 top
PC1107  10U_0402_6.3V6M  [C_0402]  106 71.64 0 top
PC1108  10U_0402_6.3V6M  [C_0402]  105.07 64.94 180 top
PC1109  10U_0402_6.3V6M  [C_0402]  114.5 63.75 180 top
PC1111  22U_0603_6.3V6M  [C_0603]  105.72 69.36 180 top
PC1112  22U_0603_6.3V6M  [C_0603]  110.96 71.13 180 top
PC1113  22U_0603_6.3V6M  [C_0603]  103.37 70.58 180 top
PC1114  22U_0603_6.3V6M  [C_0603]  106.7 70.58 0 top
PC1115  22U_0603_6.3V6M  [C_0603]  105.72 70.58 180 top
PC1116  22U_0603_6.3V6M  [C_0603]  111.41 69.92 0 top
PC1132  1U_0201_6.3V6M  [C_0201]  110.6 73.8 0 top
PC1133  1U_0201_6.3V6M  [C_0201]  108.24 74.36 0 top
PC1134  1U_0201_6.3V6M  [C_0201]  103.52 74.36 0 top
PC1135  1U_0201_6.3V6M  [C_0201]  108.24 73.8 0 top
PC1136  1U_0201_6.3V6M  [C_0201]  110.6 74.36 0 top
PC1137  1U_0201_6.3V6M  [C_0201]  114.79 60.85 180 top
PC1138  1U_0201_6.3V6M  [C_0201]  96.43 73.8 0 top
PC1139  1U_0201_6.3V6M  [C_0201]  105.88 74.36 0 top
PC1140  1U_0201_6.3V6M  [C_0201]  98.54 61.04 0 top
PC1141  1U_0201_6.3V6M  [C_0201]  101.15 74.36 0 top
PC1142  1U_0201_6.3V6M  [C_0201]  101.15 73.8 0 top
PC1143  1U_0201_6.3V6M  [C_0201]  105.92 61.6 180 top
PC1144  1U_0201_6.3V6M  [C_0201]  112.4 61.35 180 top
PC1145  1U_0201_6.3V6M  [C_0201]  114.79 61.44 180 top
PC1146  1U_0201_6.3V6M  [C_0201]  98.79 74.36 0 top
PC1162  1U_0201_6.3V6M  [C_0201]  112.4 60.76 180 top
PC1163  1U_0201_6.3V6M  [C_0201]  98.79 73.8 0 top
PC1164  1U_0201_6.3V6M  [C_0201]  105.88 73.8 0 top
PC1165  1U_0201_6.3V6M  [C_0201]  103.4 60.95 180 top
PC1166  1U_0201_6.3V6M  [C_0201]  103.4 61.51 180 top
PC1167  1U_0201_6.3V6M  [C_0201]  105.92 61.03 180 top
PC1168  1U_0201_6.3V6M  [C_0201]  98.52 61.82 0 top
PC1169  1U_0201_6.3V6M  [C_0201]  96.43 74.36 0 top
PC1170  1U_0201_6.3V6M  [C_0201]  103.52 73.8 0 top
PC1171  330U_D2_2.5V_R6M  [C_D2]  97.72 71.17 270 top
PC1172  22U_0603_6.3V6M  [C_0603]  110.96 72.33 180 top
PC1173  22U_0603_6.3V6M  [C_0603]  112.04 72.46 270 top
PC1174  22U_0603_6.3V6M  [C_0603]  103.38 66.94 180 top
PC1175  22U_0603_6.3V6M  [C_0603]  105.73 66.94 180 top
PC1176  22U_0603_6.3V6M  [C_0603]  111.41 67.51 0 top
PC1177  22U_0603_6.3V6M  [C_0603]  110.46 66.29 180 top
PC1178  22U_0603_6.3V6M  [C_0603]  106.7 66.94 0 top
PC1179  22U_0603_6.3V6M  [C_0603]  111.42 66.3 0 top
PC1180  22U_0603_6.3V6M  [C_0603]  110.46 68.72 180 top
PC1181  22U_0603_6.3V6M  [C_0603]  110.45 67.5 180 top
PC1201  0.01UF_0402_25V7K  [C_0402]  38.89 103.6 0 bottom
PC1202  0.47U_0402_25V6K  [C_0402]  43.35 113.59 270 top
PC1203  1500P_0402_50V7K  [C_0402]  50.47 120.6 90 top
PC1204  0.1U_0402_25V6  [C_0402]  56.61 100.41 0 top
PC1205  100P_0402_50V8J  [C_0402]  48.23 103.4 0 bottom
PC1206  220P_0402_50V8J  [C_0402]  49.2 100.69 270 bottom
PC1207  1200P_0402_50V7K  [C_0402]  47.02 105.75 180 bottom
PC1208  1000P_0402_50V7K  [C_0402]  17.5 124.74 0 bottom
PC1209  0.1U_0402_25V6  [C_0402]  20.35 123.65 90 bottom
PC1210  1500P_0402_50V7K  [C_0402]  26.7 120.41 90 top
PC1211  100P_0402_50V8J  [C_0402]  42.46 99.54 270 bottom
PC1212  100P_0402_50V8J  [C_0402]  39.78 100.8 180 bottom
PC1213  1200P_0402_50V7K  [C_0402]  39.78 102.58 180 bottom
PC1214  0.01UF_0402_25V7K  [C_0402]  27.15 103.02 0 bottom
PC1215  100P_0402_50V8J  [C_0402]  17.5 120.04 0 bottom
PC1216  100P_0402_50V8J  [C_0402]  21.23 123.65 90 bottom
PC1217  1500P_0402_50V7K  [C_0402]  86.97 112.42 0 bottom
PC1700  2200P_0402_50V7K  [C_0402]  63.93 84.99 180 top
PC1701  0.01UF_0402_25V7K  [C_0402]  63.93 82.37 270 top
PC1702  0.1U_0402_25V6  [C_0402]  66.56 77.9 90 top
PC1703  1000P_0402_50V7K  [C_0402]  64.8 86.78 270 top
PC1704  3300P_0402_25V7K  [C_0402]  63.72 83.37 0 top
PC1705  2200P_0402_50V7K  [C_0402]  63.03 82.37 270 top
PC1706  470P_0402_50V8J  [C_0402]  60.13 81.8 0 bottom
PC1707  1000P_0402_50V7K  [C_0402]  63.04 87.65 270 top
PC1708  1000P_0402_50V7K  [C_0402]  60.12 84.46 0 bottom
PC1709  0.015U_0402_16V7K  [C_0402]  65.5 83.21 90 top
PC1710  100P_0402_50V8J  [C_0402]  67.28 84.12 180 top
PC1711  1000P_0402_50V7K  [C_0402]  62.16 88.47 270 top
PC1712  2200P_0402_50V7K  [C_0402]  60.14 89.13 270 bottom
PC1713  1000P_0402_50V7K  [C_0402]  61.01 75.61 0 top
PC1714  47P_0402_50V8J  [C_0402]  57.73 88.37 0 top
PC1715  470P_0402_50V8J  [C_0402]  60.39 90.16 270 top
PC1716  2200P_0402_50V7K  [C_0402]  58.64 90.14 270 top
PC1717  47P_0402_50V8J  [C_0402]  57.81 73.93 180 top
PC1718  470P_0402_50V8J  [C_0402]  59.81 85.5 180 bottom
PC1719  2200P_0402_50V7K  [C_0402]  60.98 73.83 0 top
PC1720  470P_0402_50V8J  [C_0402]  58.64 72.16 90 top
PC1721  2200P_0402_50V7K  [C_0402]  56.9 72.16 90 top
PC1722  470P_0402_50V8J  [C_0402]  58.62 78.68 90 bottom
PC1723  0.1U_0402_25V7K  [C_0402]  56.31 84.53 90 bottom
PC1724  68P_0402_50V8J  [C_0402]  56.02 89.26 180 top
PC1725  680P_0402_50V7K  [C_0402]  55.11 88.39 0 top
PC1726  68P_0402_50V8J  [C_0402]  55.15 76.08 180 top
PC1727  0.1U_0402_25V7K  [C_0402]  56.59 79.19 90 bottom
PC1728  680P_0402_50V7K  [C_0402]  55.17 76.97 180 top
PC1729  0.1U_0402_25V6  [C_0402]  53.67 84.89 0 bottom
PC1730  0.01U_0402_50V7K  [C_0402]  54.58 84 180 bottom
PC1731  0.1U_0402_25V6  [C_0402]  52.45 78.17 180 bottom
PC1732  1U_0603_10V6K  [C_0603]  51.97 83.69 180 top
PC1733  0.022U_0402_25V7K  [C_0402]  54.12 89.26 270 top
PC1734  0.022U_0402_25V7K  [C_0402]  53.35 76.99 180 top
PC1735  0.022U_0402_25V7K  [C_0402]  53.23 89.26 270 top
PC1736  0.022U_0402_25V7K  [C_0402]  52.35 89.26 270 top
PC1737  0.022U_0402_25V7K  [C_0402]  54.03 90.13 180 top
PC1800  0.1U_0402_25V7K  [C_0402]  36.67 58.33 180 bottom
PC1801  0.1U_0402_25V7K  [C_0402]  36.67 57.44 180 bottom
PC1802  1000P_0402_50V7K  [C_0402]  36.66 56.56 180 bottom
PC1803  1000P_0402_50V7K  [C_0402]  36.66 55.67 180 bottom
PC1804  100U 20V M D ESR55M TQC H2.8  [C_D]  63.1 92.61 0 bottom
PC1805  100U 20V M D ESR55M TQC H2.8  [C_D]  45.64 73.59 0 bottom
PC1806  2200P_0402_50V7K  [C_0402]  74.14 102.39 0 top
PC1807  0.1U_0402_25V7K  [C_0402]  72.58 101.67 90 top
PC1808  4.7U_0603_25VAK  [C_0603]  73.55 98.86 0 bottom
PC1809  4.7U_0603_25VAK  [C_0603]  73.55 98.86 0 top
PC1810  4.7U_0603_25VAK  [C_0603]  74.12 100.07 0 top
PC1811  4.7U_0603_25VAK  [C_0603]  74.1 101.27 0 top
PC1812  1U_0603_25V7K  [C_0603]  69.11 102.38 180 bottom
PC1813  0.22U_0603_25V7K  [C_0603]  71.51 103.09 270 bottom
PC1814  2.2U_0603_10V7K  [C_0603]  66.35 96.87 270 top
PC1815  2200P_0603_50V7K  [C_0603]  74.98 92.4 270 top
PC1816  2200P_0402_50V7K  [C_0402]  84.77 102.44 90 top
PC1817  0.1U_0402_25V7K  [C_0402]  83.87 102.44 90 top
PC1818  4.7U_0603_25VAK  [C_0603]  83.14 100.18 270 bottom
PC1819  4.7U_0603_25VAK  [C_0603]  83.14 100.18 270 top
PC1820  4.7U_0603_25VAK  [C_0603]  81.6 102.46 90 top
PC1821  4.7U_0603_25VAK  [C_0603]  82.8 102.47 90 top
PC1822  1U_0603_25V7K  [C_0603]  77.16 104.29 270 top
PC1823  0.22U_0603_25V7K  [C_0603]  80.38 103.84 270 top
PC1824  2.2U_0603_10V7K  [C_0603]  77.26 99.59 270 top
PC1825  2200P_0603_50V7K  [C_0603]  83.61 94.06 180 top
PC1826  15U_B2_25VM_R100M  [C_B2]  74.68 100.91 270 bottom
PC1828  15U_B2_25VM_R100M  [C_B2]  81.32 103.14 0 bottom
PC1900  1U_0603_25V7K  [C_0603]  84.49 98.12 270 bottom
PC1901  2200P_0402_50V7K  [C_0402]  88.11 101.99 0 top
PC1902  0.1U_0402_25V7K  [C_0402]  88.18 104.06 0 top
PC1903  4.7U_0603_25VAK  [C_0603]  88.17 103.02 0 bottom
PC1904  4.7U_0603_25VAK  [C_0603]  88.17 103.02 0 top
PC1905  4.7U_0603_25VAK  [C_0603]  87.1 102.5 90 top
PC1906  4.7U_0603_25VAK  [C_0603]  85.9 102.49 90 top
PC1907  0.22U_0603_25V7K  [C_0603]  84.6 99.95 0 top
PC1908  2.2U_0603_10V7K  [C_0603]  87.87 94.49 90 top
PC1909  2200P_0603_50V7K  [C_0603]  91.33 95.12 180 top
PC1910  2200P_0402_50V7K  [C_0402]  96.48 102.09 0 top
PC1911  0.1U_0402_25V7K  [C_0402]  94.25 103.65 180 top
PC1912  4.7U_0603_25VAK  [C_0603]  96.52 103.13 0 bottom
PC1913  4.7U_0603_25VAK  [C_0603]  96.52 103.14 0 top
PC1914  4.7U_0603_25VAK  [C_0603]  94.19 102.61 180 top
PC1915  4.7U_0603_25VAK  [C_0603]  94.21 101.41 180 top
PC1916  1U_0603_25V7K  [C_0603]  93.93 98.36 270 bottom
PC1917  0.22U_0603_25V7K  [C_0603]  95.68 100.2 180 top
PC1918  2.2U_0603_10V7K  [C_0603]  97.15 96.16 0 top
PC1919  2200P_0603_50V7K  [C_0603]  97.18 92.91 0 top
PC1920  15U_B2_25VM_R100M  [C_B2]  86.33 103.14 0 bottom
PC1922  15U_B2_25VM_R100M  [C_B2]  93.27 102.78 90 bottom
PC2000  1U_0603_25V7K  [C_0603]  41.86 64.02 270 bottom
PC2001  2200P_0402_50V7K  [C_0402]  43.56 67.72 180 top
PC2002  0.1U_0402_25V7K  [C_0402]  43.56 66.83 180 top
PC2003  4.7U_0603_25VAK  [C_0603]  45.49 68.17 0 top
PC2004  4.7U_0603_25VAK  [C_0603]  45.49 69.39 0 top
PC2005  4.7U_0603_25VAK  [C_0603]  45.49 68.17 0 bottom
PC2006  4.7U_0603_25VAK  [C_0603]  45.49 69.39 0 bottom
PC2007  0.22U_0603_25V7K  [C_0603]  40.88 66.38 0 bottom
PC2008  2.2U_0603_10V7K  [C_0603]  44.81 60.32 0 bottom
PC2009  2200P_0603_50V7K  [C_0603]  48.38 60.7 0 bottom
PC2010  2200P_0402_50V7K  [C_0402]  105.79 94.23 180 top
PC2011  0.1U_0402_25V7K  [C_0402]  105.81 93.36 180 top
PC2012  4.7U_0603_25VAK  [C_0603]  105.72 95.27 180 bottom
PC2013  4.7U_0603_25VAK  [C_0603]  105.72 95.27 180 top
PC2014  4.7U_0603_25VAK  [C_0603]  105.72 96.47 180 top
PC2015  4.7U_0603_25VAK  [C_0603]  105.71 97.68 180 top
PC2016  1U_0603_25V7K  [C_0603]  104.11 90.8 270 bottom
PC2017  0.22U_0603_25V7K  [C_0603]  103.02 93.1 0 bottom
PC2018  2.2U_0603_10V7K  [C_0603]  106.93 87.2 0 bottom
PC2019  2200P_0603_50V7K  [C_0603]  116.94 94.31 90 bottom
PC2020  0.1U_0402_25V6  [C_0402]  103.72 94.22 0 bottom
PC2021  0.1U_0402_25V6  [C_0402]  42.56 68.01 0 bottom
PC2022  4.7U_0603_25VAK  [C_0603]  45.49 70.61 0 bottom
PC2023  4.7U_0603_25VAK  [C_0603]  45.49 70.61 0 top
PC2024  15U_B2_25VM_R100M  [C_B2]  107.69 95.96 180 bottom
PC2026  330U_D2_2.5V_R6M  [C_D2]  88.63 90.18 180 top
PC2027  10U_0402_6.3V6M  [C_0402]  89.63 65.55 180 top
PC2028  10U_0402_6.3V6M  [C_0402]  89.06 67.32 180 top
PC2029  10U_0402_6.3V6M  [C_0402]  89.9 67.32 0 top
PC2030  10U_0402_6.3V6M  [C_0402]  92.57 67.32 180 top
PC2031  10U_0402_6.3V6M  [C_0402]  92.42 66.43 180 top
PC2032  0.1U_0402_25V6  [C_0402]  97.39 102.09 180 bottom
PC2033  0.1U_0402_25V6  [C_0402]  89.03 101.99 180 bottom
PC2034  0.1U_0402_25V6  [C_0402]  72.58 102.58 270 bottom
PC2035  0.1U_0402_25V6  [C_0402]  84.27 101.1 180 bottom
PC2036  100P_0402_50V8J  [C_0402]  179.68 3.14 270 bottom
PC2037  100P_0402_50V8J  [C_0402]  36.66 59.21 180 bottom
PC2038  100P_0402_50V8J  [C_0402]  157.48 57.75 270 bottom
PC2039  100P_0402_50V8J  [C_0402]  166.86 2.49 0 top
PC2040  100P_0402_50V8J  [C_0402]  105.13 6.37 270 bottom
PC2048  100P_0402_50V8J  [C_0402]  86.91 5.28 90 top
PC2049  100P_0402_50V8J  [C_0402]  87.8 5.28 90 top
PC2050  100P_0402_50V8J  [C_0402]  58.78 5.5 270 top
PC2051  100P_0402_50V8J  [C_0402]  36.66 60.1 180 bottom
PC2052  100P_0402_50V8J  [C_0402]  105.22 96.35 180 bottom
PC2053  100P_0402_50V8J  [C_0402]  74.14 103.28 0 top
PC2054  100P_0402_50V8J  [C_0402]  94.25 104.55 180 top
PC2055  100P_0402_50V8J  [C_0402]  180.58 3.14 270 bottom
PD1  -  [TVNST52302AB0_SOT523-3]  3.54 12.6 90 top
PD2  -  [TVNST52302AB0_SOT523-3]  3.54 10.57 90 top
PD3  BAS40CW SOT-323  [DB3J315E0L_SMINI3-F2-B3]  297.97 9.11 0 top
PD4  -  [AZC199-02SPR7G_SOT23-3]  63.78 126.2 180 top
PD5  5A 100V 15UA 0.88V TO227-3  [PDS5100H-13_POWERDI5-3]  58.58 117.82 0 top
PD6  -  [DFLS160-7_POWERDI123-2]  65.94 121.68 0 top
PD100  -  [RB520SM-30T2R_EMD2-2]  121.14 131.64 270 bottom
PD901  30MA_30V_0.5UA_0.4V_SOD323-2  [D_SOD323-2]  15.33 39.79 90 bottom
PD903  -  [RB520SM-30T2R_EMD2-2]  11.76 41.67 90 bottom
PD904  30MA_30V_0.5UA_0.4V_SOD323-2  [D_SOD323-2]  13.55 39.79 90 bottom
PD905  -  [BAT54CW_SOT323-3]  9.51 47.27 270 top
PD906  DFLS160-7_POWERDI123-2  [SMF22A-SOD123FL-2-S]  19.73 45.73 270 top
PD1202  5A 100V 15UA 0.88V TO227-3  [PDS5100H-13_POWERDI5-3]  53.55 113.06 180 top
PD1205  30MA_30V_0.5UA_0.4V_SOD323-2  [D_SOD323-2]  44.35 105.25 180 bottom
PD1801  -  [BAT54CW_SOT323-3]  38.28 108.75 270 bottom
PH1700  100K_0402_1%_TSM0B104F4251RZ  [R_0402]  117.61 90.12 90 bottom
PH1701  220K_0402_5%_ERTJ0EV224J  [R_0402]  71.8 90.73 90 bottom
PH1702  220K_0402_5%_ERTJ0EV224J  [R_0402]  53.36 68.34 180 bottom
PH1703  220K_0402_5%_ERTJ0EV224J  [R_0402]  75.86 96.69 270 bottom
PH1704  220K_0402_5%_ERTJ0EV224J  [R_0402]  49.7 68.4 90 bottom
PJP1  PAD-OPEN1X1M  [JUMP_43X39]  131.98 86.7 90 top
PJP2  PAD-OPEN1X1M  [JUMP_43X39]  144.05 78.32 270 top
PJP3  -  [JUMP_43X79]  195.84 21.03 270 top
PJP7  PAD-OPEN1X1M  [JUMP_43X39]  25.17 85.31 0 top
PJP8  PAD-OPEN 1X3M  [JUMP_43X118]  39.67 75.93 90 bottom
PJP12  PAD-OPEN1X1M  [JUMP_43X39]  137.06 106.9 0 bottom
PJP13  PAD-OPEN1X2M  [JUMP_43X79]  118.03 111.45 270 top
PJP14  PAD-OPEN1X2M  [JUMP_43X79]  19 58.85 180 top
PJP15  PAD-OPEN1X1M  [JUMP_43X39]  327.38 22.12 0 top
PJP16  PAD-OPEN1X1M  [JUMP_43X39]  337.12 21.68 0 top
PJP17  PAD-OPEN1X2M  [JUMP_43X79]  328 18.82 180 top
PJP18  PAD-OPEN1X1M  [JUMP_43X39]  336.9 18.69 0 top
PJP19  PAD-OPEN1X1M  [JUMP_43X39]  349.23 43.52 45 bottom
PJP20  PAD-OPEN1X1M  [JUMP_43X39]  312.14 11.2 0 top
PJP21  PAD-OPEN1X1M  [JUMP_43X39]  312.14 13.49 0 top
PJP22  PAD-OPEN1X1M  [JUMP_43X39]  307.39 37.57 270 top
PJP31  PAD-OPEN1X3M  [JUMP_43X118]  364.03 8.75 90 top
PJP32  PAD-OPEN1X1M  [JUMP_43X39]  260.51 9.87 90 top
PJP33  PAD-OPEN1X1M  [JUMP_43X39]  262.43 18.87 90 top
PJP34  PAD-OPEN1X2M  [JUMP_43X79]  260.25 20.28 270 bottom
PJP35  PAD-OPEN1X1M  [JUMP_43X39]  140.75 11.77 270 top
PJP36  PAD-OPEN1X2M  [JUMP_43X79]  291.51 9.25 90 top
PJP37  PAD-OPEN1X1M  [JUMP_43X39]  312.85 74.62 90 top
PJP38  PAD-OPEN1X1M  [JUMP_43X39]  191.44 7.82 90 top
PJP39  PAD-OPEN1X3M  [JUMP_43X118]  198.89 7.52 0 top
PJP40  PAD-OPEN1X2M  [JUMP_43X79]  282.66 9.04 180 top
PJP41  PAD-OPEN1X3M  [JUMP_43X118]  311.32 65.73 270 top
PJP42  PAD-OPEN1X1M  [JUMP_43X39]  332.96 46.42 0 top
PJP100  PAD-OPEN 1X2M~D  [JUMP_43X79]  80.57 5.12 0 bottom
PJP101  PAD-OPEN 1X2M~D  [JUMP_43X79]  130.96 127.91 90 top
PJP102  -  [JUMP_43X118]  106 9.44 0 bottom
PJP103  -  [JUMP_43X118]  136.79 126.87 270 bottom
PJP200  -  [JUMP_43X118]  61.7 8.58 90 bottom
PJP201  -  [JUMP_43X39]  46.98 10.29 90 top
PJP202  PAD-OPEN 1X2M~D  [JUMP_43X79]  41.77 4.61 90 bottom
PJP301  PAD-OPEN 1X2M~D  [JUMP_43X79]  164.19 4.15 0 top
PJP302  -  [JUMP_43X118]  183.5 11.15 0 bottom
PJP391  PAD-OPEN1X1M  [JUMP_43X39]  251.73 33.2 90 top
PJP401  -  [JUMP_43X118]  143.43 66.02 90 bottom
PJP402  PAD-OPEN 1X2M~D  [JUMP_43X79]  158.79 61.6 270 bottom
PJP501  PAD-OPEN1X1M  [JUMP_43X39]  117.89 7.34 270 bottom
PJP502  PAD-OPEN1X1M  [JUMP_43X39]  125.65 8.51 0 bottom
PJP503  PAD-OPEN1X1M  [JUMP_43X39]  152.88 128.93 0 top
PJP504  PAD-OPEN1X1M  [JUMP_43X39]  145.79 129.69 180 top
PJP505  PAD-OPEN1X1M  [JUMP_43X39]  67.67 9.15 0 bottom
PJP506  PAD-OPEN1X1M  [JUMP_43X39]  76.02 9.31 0 bottom
PJP901  JUMP_43X118  [JUMP_43X118-NPM]  19.6 45.06 270 bottom
PJP1202  -  [JUMP_43X118]  23.86 122.77 0 top
PJP2000  -  [JUMP_43X118]  42.76 56.03 180 bottom
PJP2001  -  [JUMP_43X118]  105 99.24 90 bottom
PJPDC1  CVILU_CI0805M1HRC-NH  [CVILU_CI0805M1HRC-NH_5P-T]  62.5 121.2 270 bottom
PL1  FBMJ4516HS720NT_2P  [TAIYO_FBMJ4516HS720NT_2P]  16.54 7.2 270 top
PL2  FBMJ4516HS720NT_2P  [TAIYO_FBMJ4516HS720NT_2P]  14.13 7.2 270 top
PL3  BLM15AG102SN1D_2P  [MURAT_BLM15AG102SN1D_2P]  66.2 127.09 180 top
PL4  -  [5A_Z80_0805_2P]  66.1 117.09 0 bottom
PL100  1.5UH_9A_20%_7X7X3_M  [L_7X7X3_M_2P]  95.52 4.25 90 bottom
PL101  2.2UH +-20% 7.8A 7X7X3 MOLDING  [CYNTE_PCMC063T-1R5MN_2P]  126.54 130.24 0 bottom
PL201  1UH_11A_20%_7X7X3_M  [L_7X7X3_M_2P]  50.93 7.28 0 bottom
PL301  0.68UH_7.9A_20%_5X5X3_M  [L_5X5X3_M_2P]  173.03 4.1 0 bottom
PL302  -  [5A_Z80_0805_2P]  163.53 5.1 0 bottom
PL401  1UH_PCMB042T-1R0MS_4.5A_20%  [CYNTE_PCMB042T-1R0MS_2P]  145.94 58.33 90 bottom
PL405  3A_Z120_40M_0603_2P  [3A_Z120_0603_2P]  161.41 61.99 270 bottom
PL501  1UH_1277AS-H-1R0N-P2_3.3A_30%  [MAG_MLV-FY12N1R0M-O1L_2P]  124.86 4.14 90 bottom
PL502  3A_Z120_40M_0603_2P  [3A_Z120_0603_2P]  116.05 8.33 270 bottom
PL901  1UH +-20% 6.6A 5X5X3 MOLDING  [MAGLA_MMD-05CZ-1R0M-M7L_2P]  19.57 42.63 90 bottom
PL902  1UH_MMD-10DZ-1R0M-X1A_18A_20%  [MAG_MMD-10DZ-1R0M-X1A_2P]  17.28 27.79 270 bottom
PL1201  -  [5A_Z80_0805_2P]  17.23 121.62 0 bottom
PL1202  -  [5A_Z80_0805_2P]  17.23 123.4 0 bottom
PL1800  -  [5A_Z80_0805_2P]  38.32 59.37 90 bottom
PL1801  -  [5A_Z80_0805_2P]  40.12 59.37 90 bottom
PL1802  0.15UH_MMD-06CZER15MEX5L__35A_20%  [L_7X7X3_M]  76 93.24 270 bottom
PL1803  0.15UH_MMD-06CZER15MEX5L__35A_20%  [L_7X7X3_M]  83.52 93.25 270 bottom
PL1900  0.15UH_MMD-06CZER15MEX5L__35A_20%  [L_7X7X3_M]  91.04 93.4 270 bottom
PL1901  0.15UH_MMD-06CZER15MEX5L__35A_20%  [L_7X7X3_M]  98.57 93.5 270 bottom
PL2000  0.15UH_MMD-06CZER15MEX5L__35A_20%  [L_7X7X3_M]  51.03 64.14 0 bottom
PL2001  0.47UH_MMD05CZR47M_12A_20%  [MAG_MMD05CZR47M_4P]  114.19 92.98 270 bottom
PL2002  -  [5A_Z80_0805_2P]  66.1 118.9 0 bottom
PQ1  -  [DMN65D8LDW-7_SOT363-6]  68.86 109.44 90 top
PQ2  -  [FDV301N-G_SOT23-3]  67.09 124.71 270 top
PQ3  MMST3904-7-F_SOT323~D  [MMST3904-7-F_SOT323-3]  71.36 124.65 270 top
PQ4  -  [AON7409_DFN8-5]  60.48 114.26 270 top
PQ5  -  [AO3409_SOT23-3]  59.98 108.44 270 bottom
PQ6  L2N7002WT1G 1N SC-70-3  [DMN65D8LW-7_SOT323-3]  72.05 120.88 90 top
PQ7  L2N7002WT1G 1N SC-70-3  [DMN65D8LW-7_SOT323-3]  61.37 109.95 90 top
PQ8  L2N7002WT1G 1N SC-70-3  [DMN65D8LW-7_SOT323-3]  77.4 117.19 0 top
PQ9  -  [AON7409_DFN8-5]  67.29 117.7 90 top
PQ902  AON6354_N_DFN56-8-5  [Q_N_DFN56-8-5]  17.1 35.54 270 top
PQ903  AON6354_N_DFN56-8-5  [Q_N_DFN56-8-5]  19.59 25.73 90 top
PQ906  -  [AON7409_DFN8-5]  21.62 4.15 90 top
PQ909  L2N7002WT1G 1N SC-70-3  [DMN65D8LW-7_SOT323-3]  8.26 41.62 0 bottom
PQ1201  -  [DMN65D8LDW-7_SOT363-6]  56.6 104.69 0 top
PQ1202  -  [AON7409_DFN8-5]  52.15 116.39 90 top
PQ1203  -  [AO3409_SOT23-3]  55.19 121.21 90 top
PQ1204  -  [DMN65D8LDW-7_SOT363-6]  67.19 102.45 0 top
PQ1205  L2N7002WT1G 1N SC-70-3  [DMN65D8LW-7_SOT323-3]  64.52 107.01 90 top
PQ1206  -  [AON7409_DFN8-5]  25.43 122.99 270 bottom
PQ1207  -  [DMN66D0LDW-7_SOT363-6]  69.15 106.26 180 bottom
PQ1208  -  [DMN66D0LDW-7_SOT363-6]  65.97 106.14 180 bottom
PQ1209  -  [DMN65D8LDW-7_SOT363-6]  26.64 105.89 0 bottom
PQ1210  -  [DMN66D0LDW-7_SOT363-6]  78.93 111.34 180 bottom
PQ1211  -  [DMN66D0LDW-7_SOT363-6]  85.28 111.34 180 bottom
PQ1212  L2N7002WT1G 1N SC-70-3  [DMN65D8LW-7_SOT323-3]  45.5 99.66 180 bottom
PQ1213  -  [AON7409_DFN8-5]  44.86 114.64 270 top
PQ1214  -  [DMN65D8LDW-7_SOT363-6]  63.76 100.62 90 top
PQ1215  -  [AO3409_SOT23-3]  43.46 110.45 180 top
PQ1216  L2N7002WT1G 1N SC-70-3  [DMN65D8LW-7_SOT323-3]  76.63 108.04 0 bottom
PQ1302  AON6962 2N DFN5X6D-8  [AON6992_DFN5X6D-8-7]  21.12 16.97 90 top
PR1  100K_0402_5%  [R_0402]  5.89 41.81 90 bottom
PR2  1K_0402_5%  [R_0402]  297.34 5.17 90 top
PR3  0_0402_5%  [R_0402]  67.21 127.09 0 top
PR4  2.2K_0402_5%  [R_0402]  71.24 126.61 90 top
PR5  33_0402_5%  [R_0402]  68.99 127.09 0 top
PR6  100K_0402_1%  [R_0402]  72.26 122.96 180 top
PR7  10K_0402_1%  [R_0402]  72.24 127.48 270 top
PR8  15K_0402_1%  [R_0402]  74.04 122.96 180 top
PR10  300K_0402_5%  [R_0402]  55.72 109.21 270 bottom
PR11  499K_0402_1%  [R_0402]  57.31 109.95 0 top
PR12  1M_0402_1%  [R_0402]  70.64 120.41 90 top
PR13  4.7K_0805_5%  [R_0805]  69.67 116.64 270 top
PR14  100K_0402_5%  [R_0402]  64.99 116.23 0 top
PR15  100K_0402_5%  [R_0402]  64.61 109.63 0 top
PR16  49.9K_0402_1%  [R_0402]  59.21 109.95 0 top
PR17  100K_0402_5%  [R_0402]  69.12 111.98 180 top
PR18  1M_0402_1%  [R_0402]  69.55 122.26 0 top
PR19  0_0402_5%  [R0402_0OHM]  70.13 110.83 270 top
PR20  0_0402_5%  [R0402_0OHM]  64.61 110.51 0 top
PR21  0_0402_5%  [R0402_0OHM]  75.42 115.03 180 top
PR22  0_0402_5%  [R0402_0OHM]  75.37 118.56 180 top
PR23  0_0402_5%  [R0402_0OHM]  73.21 118.56 180 top
PR24  100K_0402_5%  [R_0402]  65.58 111.38 180 top
PR25  0_0402_5%  [R0402_0OHM]  64.61 108.74 0 top
PR26  0_0402_5%  [R0402_0OHM]  80.15 117 180 top
PR27  100K_0402_5%  [R_0402]  76.3 118.64 0 top
PR28  100K_0402_5%  [R_0402]  79.31 116.06 270 top
PR29  0_0402_5%  [R0402_0OHM]  77.64 114.1 180 top
PR30  100K_0402_5%  [R_0402]  75.13 120.33 90 top
PR100  0_0603_5%  [R_0603]  88.55 3.93 0 bottom
PR102  499K_0402_1%  [R_0402]  86.07 9.99 180 bottom
PR103  499K_0402_1%  [R_0402]  86.07 10.89 180 bottom
PR104  0_0402_5%  [R0402_0OHM]  91.12 10.41 0 top
PR105  0_0402_5%  [R0402_0OHM]  91.03 9.04 0 top
PR106  4.7_1206_5%  [R_1206]  91.61 4.72 180 top
PR107  100K_0402_5%  [R_0402]  84.94 8.9 270 bottom
PR108  1K_0402_5%  [R_0402]  88.71 11.39 270 bottom
PR111  0_0603_5%  [R_0603]  126.81 130.85 0 top
PR112  4.7_1206_5%  [R_1206]  125.05 126.77 180 bottom
PR113  100K_0402_5%  [R_0402]  121.54 135.12 0 top
PR114  0_0402_5%  [R0402_0OHM]  119.5 126.9 180 bottom
PR116  1M_0402_1%  [R_0402]  118.59 127.79 0 bottom
PR117  1K_0402_5%  [R_0402]  119.89 133.47 270 top
PR119  0_0402_5%  [R0402_0OHM]  84 8.04 90 bottom
PR120  0_0402_5%  [R0402_0OHM]  83.01 8.04 90 bottom
PR202  4.7_1206_5%  [R_1206]  50.58 8.5 0 top
PR203  0_0603_5%  [R_0603]  49.22 5.89 0 top
PR204  102K_0402_1%  [R_0402]  44.88 4.52 0 bottom
PR205  0_0402_5%  [R_0402]  46.64 4.36 0 top
PR206  100K_0402_1%  [R_0402]  46.66 3.62 90 bottom
PR207  0_0402_5%  [R_0402]  45.79 3.63 90 top
PR208  0_0402_5%  [R0402_0OHM]  43.08 10.49 90 bottom
PR209  1M_0402_5%  [R_0402]  41.18 10.49 90 bottom
PR210  0_0402_5%  [R0402_0OHM]  44 10.54 90 top
PR212  1M_0402_5%  [R_0402]  42.17 10.57 90 top
PR302  1M_0402_1%  [R_0402]  166.68 9.42 90 top
PR303  4.7_1206_5%  [R_1206]  172.26 4.91 270 top
PR304  0_0603_5%  [R_0603]  170.6 2.13 90 bottom
PR306  15K_0402_1%  [R_0402]  169.66 9.65 180 bottom
PR311  20K_0402_1%  [R_0402]  169.52 10.05 0 top
PR312  15K_0402_1%  [R_0402]  167.59 10.35 270 top
PR313  100_0402_5%  [R_0402]  171.13 10.52 180 bottom
PR314  0_0402_5%  [R0402_0OHM]  171.27 9.18 0 top
PR315  0_0402_5%  [R0402_0OHM]  171.27 10.05 0 top
PR316  0_0402_5%  [R_0402]  171.27 10.92 0 top
PR402  0_0402_5%  [R0402_0OHM]  154.75 56.16 180 top
PR403  1M_0402_1%  [R_0402]  153.84 58 0 top
